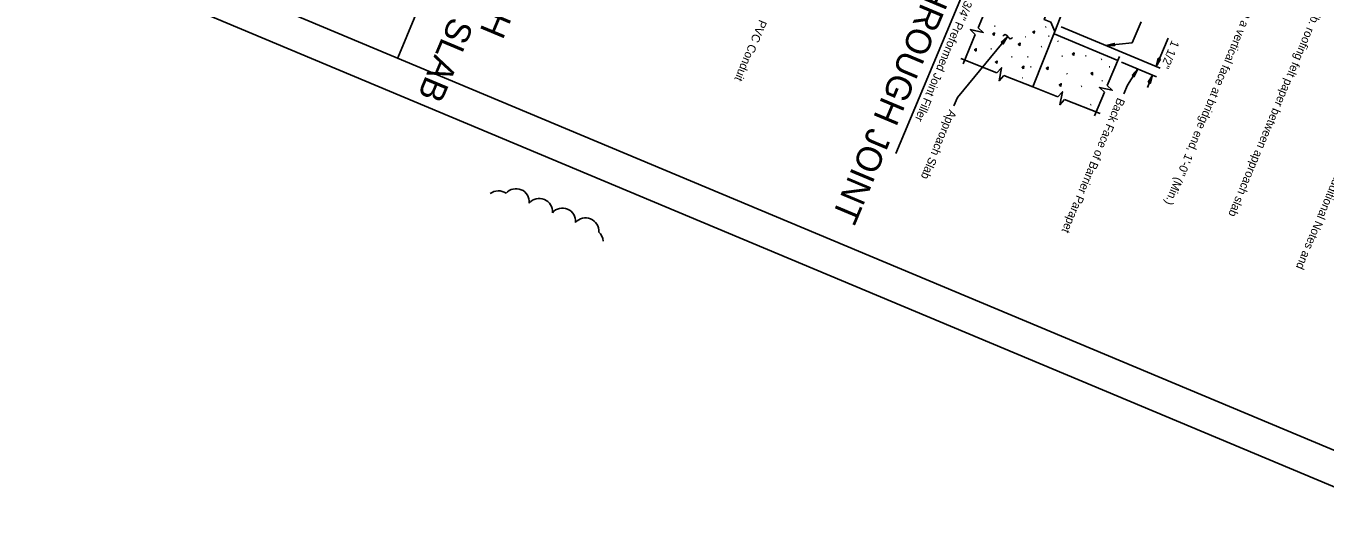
# Model space of a CAD drawing. Extents: x 1968564 to 1968711, y 796599 to 796794.
# Drawn here: x 1968563.8 to 1968641, y 796598.9 to 796627.8 of the extents above; entities that cross this region are included whole.
import ezdxf

# ---------------------------------------------------------------- set-up
doc = ezdxf.new("R2010")
doc.units = 0
for name, color, linetype in [('BR_AUTO DIMENSION', 7, 'Continuous'), ('BR_BORDER LINES', 7, 'Continuous'), ('BR_CONCRETE', 7, 'Continuous'), ('BR_DETAILS', 7, 'Continuous'), ('BR_TABLE LINES', 7, 'Continuous'), ('BR_TEXT', 7, 'Continuous'), ('Level 31', 7, 'Continuous')]:
    doc.layers.add(name, color=color, linetype=linetype)

msp = doc.modelspace()

# ---------------------------------------------------------------- linework, layer by layer
at = {"layer": 'BR_AUTO DIMENSION'}
for p, q in [((1968615.525, 796620.181), (1968619.68, 796630.089)), ((1968625.349, 796627.711), (1968631.224, 796625.247)), ((1968629.567, 796626.744), (1968630.091, 796627.993)), ((1968622.166, 796627.122), (1968619.175, 796623.508)), ((1968631.694, 796627.037), (1968630.985, 796625.347)), ((1968629.567, 796626.744), (1968628.009, 796626.595)), ((1968628.933, 796625.608), (1968631.01, 796624.737)), ((1968629.275, 796624.234), (1968629.893, 796625.205)), ((1968630.462, 796624.099), (1968630.771, 796624.837)), ((1968629.061, 796623.724), (1968629.275, 796624.234)), ((1968618.961, 796622.998), (1968619.175, 796623.508))]:
    msp.add_line(p, q, dxfattribs=at)
for points in [[(1968621.786, 796626.783), (1968622.164, 796627.119), (1968621.902, 796626.687)], [(1968628.514, 796626.568), (1968628.009, 796626.595), (1968628.5, 796626.717)], [(1968631.248, 796625.779), (1968630.985, 796625.347), (1968631.109, 796625.837)], [(1968629.561, 796624.824), (1968629.893, 796625.205), (1968629.688, 796624.743)], [(1968630.509, 796624.405), (1968630.771, 796624.837), (1968630.647, 796624.347)]]:
    msp.add_lwpolyline(points, close=True, dxfattribs=at)
for centre, start, end in [((1968591.907, 796617.172), 54.20928, 128.21746), ((1968592.962, 796617.301), 354.74601, 139.74601), ((1968594.337, 796616.724), 354.74601, 139.74601), ((1968595.713, 796616.147), 354.74601, 139.74601), ((1968597.089, 796615.57), 354.74601, 139.74601), ((1968597.362, 796614.902), 4.94704, 49.74601)]:
    msp.add_arc(centre, 0.782, start, end, dxfattribs=at)
at = {"layer": 'BR_BORDER LINES'}
for p, q in [((1968594.308, 796645.846), (1968585.928, 796625.865)), ((1968566.464, 796634.028), (1968643.927, 796601.539))]:
    msp.add_line(p, q, dxfattribs=at)
at = {"layer": 'BR_CONCRETE'}
for p, q in [((1968624.963, 796627.415), (1968623.667, 796624.134)), ((1968628.703, 796625.704), (1968624.926, 796627.288))]:
    msp.add_line(p, q, dxfattribs=at)
at = {"layer": 'BR_DETAILS'}
for p, q in [((1968620.41, 796627.652), (1968622.001, 796631.447)), ((1968621.392, 796627.744), (1968621.425, 796627.751)), ((1968624.42, 796627.689), (1968624.453, 796627.696)), ((1968619.511, 796625.509), (1968620.242, 796627.251)), ((1968621.931, 796627.203), (1968621.884, 796627.153)), ((1968622.229, 796627.044), (1968622.097, 796627.201)), ((1968622.452, 796627.077), (1968622.419, 796627.038)), ((1968623.215, 796627.109), (1968623.248, 796627.116)), ((1968624.587, 796627.148), (1968624.62, 796627.155)), ((1968621.166, 796626.396), (1968621.199, 796626.404)), ((1968624.153, 796626.523), (1968624.186, 796626.53)), ((1968625.171, 796626.829), (1968625.139, 796626.863)), ((1968621.525, 796624.965), (1968619.374, 796625.829)), ((1968622.401, 796625.915), (1968622.434, 796625.922)), ((1968623.346, 796625.911), (1968623.379, 796625.918)), ((1968625.383, 796625.958), (1968625.416, 796625.965)), ((1968626.798, 796625.969), (1968626.831, 796625.976)), ((1968627.72, 796625.77), (1968627.753, 796625.776)), ((1968628.799, 796625.935), (1968628.078, 796624.216)), ((1968623.667, 796624.134), (1968621.928, 796624.806)), ((1968623.036, 796624.667), (1968623.069, 796624.674)), ((1968623.529, 796625.321), (1968623.562, 796625.328)), ((1968625.705, 796624.893), (1968625.673, 796624.927)), ((1968628.202, 796625.319), (1968628.235, 796625.326)), ((1968625.142, 796623.536), (1968623.667, 796624.134)), ((1968626.534, 796624.165), (1968626.567, 796624.171)), ((1968627.911, 796623.815), (1968627.322, 796622.413)), ((1968627.795, 796624.482), (1968627.763, 796624.515)), ((1968627.655, 796622.56), (1968625.546, 796623.377)), ((1968627.092, 796623.074), (1968627.125, 796623.081))]:
    msp.add_line(p, q, dxfattribs=at)
for points in [[(1968620.41, 796627.652), (1968620.71, 796627.369), (1968619.942, 796627.534), (1968620.242, 796627.251)], [(1968621.367, 796627.185), (1968621.279, 796627.28), (1968621.378, 796627.341), (1968621.367, 796627.185)], [(1968623.745, 796627.296), (1968623.657, 796627.391), (1968623.757, 796627.453), (1968623.745, 796627.296)], [(1968620.285, 796626.246), (1968620.197, 796626.341), (1968620.297, 796626.403), (1968620.285, 796626.246)], [(1968622.888, 796626.58), (1968622.8, 796626.675), (1968622.899, 796626.736), (1968622.888, 796626.58)], [(1968626.1, 796625.999), (1968626.014, 796626.096), (1968626.115, 796626.156), (1968626.1, 796625.999)], [(1968621.526, 796625.514), (1968621.437, 796625.61), (1968621.537, 796625.671), (1968621.526, 796625.514)], [(1968623.113, 796625.205), (1968623.025, 796625.3), (1968623.125, 796625.361), (1968623.113, 796625.205)], [(1968621.928, 796624.806), (1968621.652, 796624.5), (1968621.801, 796625.271), (1968621.525, 796624.965)], [(1968624.558, 796625.153), (1968624.47, 796625.248), (1968624.57, 796625.309), (1968624.558, 796625.153)], [(1968627.199, 796624.824), (1968627.111, 796624.919), (1968627.211, 796624.981), (1968627.199, 796624.824)], [(1968625.546, 796623.377), (1968625.27, 796623.071), (1968625.419, 796623.842), (1968625.142, 796623.536)], [(1968625.33, 796624.162), (1968625.243, 796624.26), (1968625.344, 796624.319), (1968625.33, 796624.162)], [(1968628.078, 796624.216), (1968628.378, 796623.933), (1968627.611, 796624.098), (1968627.911, 796623.815)]]:
    msp.add_lwpolyline(points, dxfattribs=at)
for centre, radius, start, end in [((1968622.014, 796627.142), 0.103, 35.84242, 144.128), ((1968622.325, 796627.107), 0.116, 213.39757, 323.19645)]:
    msp.add_arc(centre, radius, start, end, dxfattribs=at)
at = {"layer": 'BR_TABLE LINES'}
msp.add_lwpolyline([(1968625.429, 796628.592), (1968624.963, 796627.415), (1968624.729, 796627.971), (1968624.34, 796628.134), (1968624.495, 796628.527), (1968624.884, 796628.363)], close=True, dxfattribs=at)
at = {"layer": 'Level 31'}
msp.add_lwpolyline([(1968619.541, 796765.748), (1968563.846, 796632.955), (1968644.997, 796598.919), (1968700.693, 796731.712)], close=True, dxfattribs=at)

# ---------------------------------------------------------------- texts
at = {"layer": 'BR_AUTO DIMENSION'}
for s, p in [('3/4" Preformed Joint Filler', (1968619.621, 796629.3)), ('1 1/2"', (1968631.924, 796626.94))]:
    msp.add_text(s, height=0.5, rotation=247.24601, dxfattribs=at).set_placement(p)
at = {"layer": 'BR_TEXT'}
for s, height, p in [('WING WALL  APPROACH SLAB', 1.5, (1968598.522, 796650.871)), ('SECTION THROUGH', 1.5, (1968598.361, 796645.546)), ('SECTION THROUGH JOINT', 1.5, (1968621.739, 796640.378)), ('Transition to a 5" curb with a vertical face at bridge end, 1\'-0" (Min.) ', 0.49995, (1968639.174, 796635.57)), ('Place 2 layers of 30 lb. roofing felt paper between approach slab ', 0.49995, (1968642.632, 796634.12)), ('For Schedule of Reinforcement, Quantities, and Additional Notes and ', 0.49995, (1968647.193, 796632.287)), ('2" Dia. PVC Conduit', 0.5, (1968608.255, 796630.164)), ('Back Face of Barrier Parapet', 0.5, (1968628.695, 796623.523)), ('Approach Slab', 0.5, (1968618.691, 796622.814))]:
    msp.add_text(s, height=height, rotation=247.24601, dxfattribs=at).set_placement(p)

doc.saveas('drawing.dxf')
